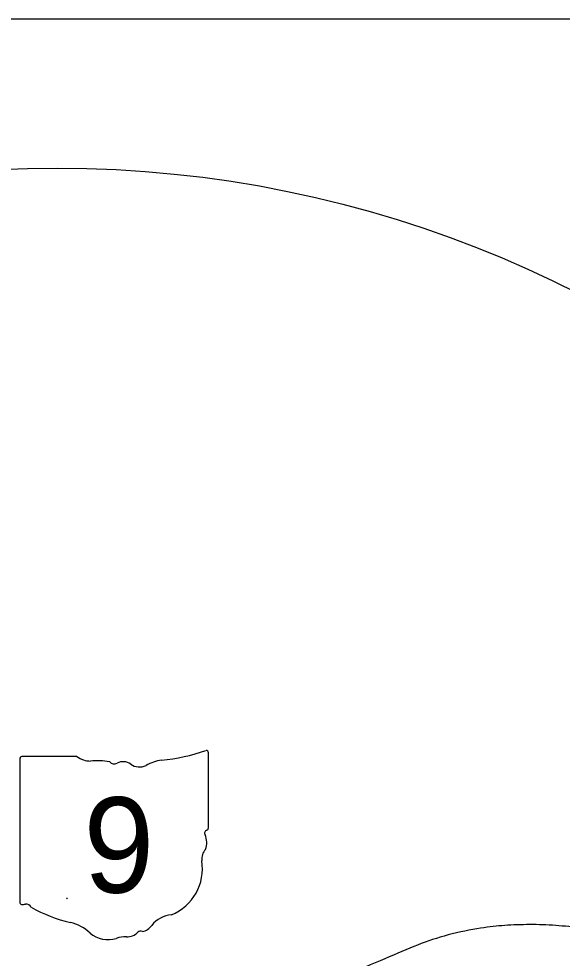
# Model space of a CAD drawing. Extents: x -740 to 1519, y 0 to 440.
# Drawn here: x 492 to 534.8, y 146.1 to 220 of the extents above; entities that cross this region are included whole.
import ezdxf

# ---------------------------------------------------------------- set-up
doc = ezdxf.new("R2010")
doc.units = 0
for name, color, linetype in [('GM_X_County_Road_Text', 7, 'Continuous'), ('GM_X_Section', 7, 'Continuous'), ('GM_X_Section_Text', 7, 'Continuous'), ('SH_Data', 7, 'Continuous')]:
    doc.layers.add(name, color=color, linetype=linetype)

msp = doc.modelspace()

# ---------------------------------------------------------------- linework, layer by layer
at = {"layer": 'GM_X_County_Road_Text'}
for p, q in [((496.558, 161.954), (492.215, 161.954)), ((506.9, 156.344), (506.9, 162.233)), ((492.069, 161.76), (492.069, 150.504)), ((506.899, 156.346), (506.9, 156.344))]:
    msp.add_line(p, q, dxfattribs=at)
for centre, radius, start, end in [((492.239, 161.784), 0.172, 98.1301, 188.1301), ((497.593, 163.261), 1.667, 231.61951, 271.11188), ((501.617, 177.301), 15.728, 275.84447, 288.90645), ((506.736, 162.257), 0.165, 351.86209, 97.738), ((498.145, 155.634), 5.983, 80.48669, 94.98827), ((499.503, 161.843), 0.481, 219.79206, 297.10237), ((500.209, 160.542), 1, 54.46668, 119.14113), ((501.499, 162.326), 1.203, 233.85621, 294.82819), ((503.623, 158.516), 3.164, 97.34618, 120.76885), ((506.862, 155.912), 0.256, 107.94398, 210.33697), ((506.724, 156.322), 0.177, 289.60381, 7.73413), ((505.236, 155.168), 1.534, 340.03296, 23.64957), ((507.492, 153.88), 1.116, 136.8065, 186.92959), ((502.498, 153.131), 3.934, 292.30889, 8.98584), ((492.24, 150.479), 0.173, 171.95839, 258.30661), ((492.267, 151.631), 1.323, 267.33899, 280.60386), ((492.537, 149.854), 0.477, 29.74838, 93.27175), ((498.559, 159.968), 11.358, 240.41292, 257.1985), ((504.157, 147.343), 2.155, 94.40312, 142.57675), ((495.173, 145.446), 3.554, 47.18416, 75.83597), ((501.427, 149.413), 1.271, 282.87319, 323.27711), ((499.017, 149.798), 2.255, 230.70037, 286.29184), ((500.484, 148.955), 1.201, 268.77702, 315.54927), ((501.571, 147.865), 0.338, 65.75173, 132.64842), ((500.32, 145.906), 1.853, 85.69512, 111.20995)]:
    msp.add_arc(centre, radius, start, end, dxfattribs=at)
at = {"layer": 'GM_X_Section'}
msp.add_line((30, 220), (640, 220), dxfattribs=at)
at = {"layer": 'GM_X_Section_Text'}
for p, q in [((501.12, 152.325), (501.12, 152.34)), ((501.122, 152.34), (501.122, 152.337)), ((501.122, 152.335), (501.122, 152.325)), ((501.129, 152.339), (501.129, 152.339)), ((501.13, 152.329), (501.13, 152.329)), ((495.763, 150.795), (495.754, 150.782)), ((495.769, 150.78), (495.769, 150.78)), ((495.775, 150.786), (495.777, 150.786)), ((495.777, 150.784), (495.775, 150.784)), ((495.78, 150.785), (495.78, 150.785)), ((495.785, 150.78), (495.785, 150.78))]:
    msp.add_line(p, q, dxfattribs=at)
for points in [[(495.755, 150.779), (495.764, 150.779), (495.764, 150.775)], [(495.768, 150.781), (495.766, 150.781), (495.766, 150.795)], [(495.766, 150.775), (495.766, 150.779), (495.768, 150.779)]]:
    msp.add_lwpolyline(points, dxfattribs=at)
msp.add_lwpolyline([(495.764, 150.794), (495.764, 150.781), (495.756, 150.781), (495.764, 150.794)], close=True, dxfattribs=at)
for points in [[(501.12, 152.34), (501.12, 152.34), (501.121, 152.34)], [(501.12, 152.326), (501.12, 152.327), (501.12, 152.327)], [(501.12, 152.327), (501.12, 152.327), (501.12, 152.327)], [(501.12, 152.327), (501.12, 152.327), (501.12, 152.327)], [(501.12, 152.327), (501.121, 152.327), (501.121, 152.327)], [(501.121, 152.325), (501.12, 152.326), (501.12, 152.326)], [(501.12, 152.326), (501.12, 152.326), (501.12, 152.326)], [(501.121, 152.325), (501.12, 152.325), (501.12, 152.325)], [(501.121, 152.34), (501.121, 152.34), (501.121, 152.34)], [(501.121, 152.34), (501.121, 152.34), (501.121, 152.34)], [(501.121, 152.34), (501.121, 152.34), (501.121, 152.34)], [(501.121, 152.34), (501.122, 152.34), (501.122, 152.34)], [(501.121, 152.338), (501.121, 152.338), (501.122, 152.339)], [(501.121, 152.336), (501.121, 152.337), (501.121, 152.338)], [(501.121, 152.334), (501.121, 152.335), (501.121, 152.336)], [(501.122, 152.333), (501.121, 152.334), (501.121, 152.334)], [(501.121, 152.327), (501.121, 152.327), (501.121, 152.327)], [(501.121, 152.327), (501.122, 152.327), (501.122, 152.327)], [(501.122, 152.325), (501.122, 152.325), (501.121, 152.325)], [(501.121, 152.325), (501.121, 152.325), (501.121, 152.325)], [(501.121, 152.324), (501.121, 152.324), (501.121, 152.325)], [(501.122, 152.324), (501.122, 152.324), (501.121, 152.324)], [(501.121, 152.324), (501.121, 152.324), (501.121, 152.324)], [(501.121, 152.324), (501.121, 152.324), (501.121, 152.324)], [(501.122, 152.339), (501.123, 152.339), (501.124, 152.34)], [(501.122, 152.34), (501.122, 152.34), (501.122, 152.34)], [(501.122, 152.34), (501.122, 152.34), (501.122, 152.34)], [(501.122, 152.34), (501.122, 152.34), (501.122, 152.34)], [(501.122, 152.337), (501.123, 152.338), (501.124, 152.339)], [(501.124, 152.336), (501.123, 152.336), (501.122, 152.335)], [(501.123, 152.332), (501.122, 152.333), (501.122, 152.333)], [(501.122, 152.327), (501.123, 152.326), (501.123, 152.326)], [(501.123, 152.324), (501.123, 152.324), (501.122, 152.325)], [(501.122, 152.325), (501.122, 152.325), (501.122, 152.325)], [(501.122, 152.325), (501.122, 152.324), (501.122, 152.324)], [(501.122, 152.324), (501.122, 152.324), (501.122, 152.324)], [(501.124, 152.338), (501.124, 152.338), (501.123, 152.338)], [(501.123, 152.338), (501.123, 152.338), (501.123, 152.337)], [(501.123, 152.337), (501.123, 152.337), (501.123, 152.336)], [(501.123, 152.336), (501.123, 152.335), (501.123, 152.335)], [(501.123, 152.335), (501.123, 152.334), (501.124, 152.334)], [(501.125, 152.332), (501.124, 152.332), (501.123, 152.332)], [(501.123, 152.326), (501.124, 152.326), (501.125, 152.326)], [(501.125, 152.324), (501.124, 152.324), (501.123, 152.324)], [(501.124, 152.34), (501.124, 152.34), (501.126, 152.34)], [(501.124, 152.339), (501.124, 152.339), (501.125, 152.34)], [(501.126, 152.339), (501.125, 152.339), (501.124, 152.338)], [(501.125, 152.338), (501.124, 152.337), (501.124, 152.336)], [(501.124, 152.334), (501.124, 152.334), (501.125, 152.333)], [(501.125, 152.34), (501.125, 152.34), (501.126, 152.34)], [(501.126, 152.338), (501.126, 152.338), (501.125, 152.338)], [(501.125, 152.338), (501.125, 152.338), (501.125, 152.338)], [(501.125, 152.333), (501.126, 152.333), (501.126, 152.333)], [(501.126, 152.331), (501.125, 152.331), (501.125, 152.332)], [(501.125, 152.326), (501.126, 152.326), (501.126, 152.326)], [(501.127, 152.324), (501.126, 152.324), (501.125, 152.324)], [(501.126, 152.34), (501.126, 152.34), (501.127, 152.34)], [(501.126, 152.34), (501.126, 152.34), (501.126, 152.34)], [(501.126, 152.34), (501.127, 152.34), (501.127, 152.34)], [(501.127, 152.338), (501.126, 152.339), (501.126, 152.339)], [(501.127, 152.338), (501.127, 152.338), (501.126, 152.338)], [(501.126, 152.333), (501.127, 152.333), (501.128, 152.332)], [(501.127, 152.331), (501.127, 152.331), (501.126, 152.331)], [(501.126, 152.326), (501.127, 152.326), (501.127, 152.326)], [(501.127, 152.34), (501.127, 152.34), (501.128, 152.34)], [(501.127, 152.34), (501.127, 152.34), (501.128, 152.34)], [(501.128, 152.338), (501.128, 152.338), (501.127, 152.338)], [(501.128, 152.338), (501.127, 152.338), (501.127, 152.338)], [(501.128, 152.33), (501.128, 152.33), (501.127, 152.331)], [(501.127, 152.326), (501.128, 152.327), (501.128, 152.327)], [(501.129, 152.325), (501.128, 152.325), (501.127, 152.324)], [(501.128, 152.34), (501.128, 152.34), (501.129, 152.34)], [(501.128, 152.34), (501.128, 152.34), (501.128, 152.34)], [(501.128, 152.34), (501.128, 152.34), (501.128, 152.34)], [(501.128, 152.34), (501.129, 152.34), (501.129, 152.34)], [(501.129, 152.338), (501.129, 152.338), (501.128, 152.338)], [(501.129, 152.338), (501.128, 152.338), (501.128, 152.338)], [(501.128, 152.338), (501.128, 152.338), (501.128, 152.338)], [(501.128, 152.338), (501.128, 152.338), (501.128, 152.338)], [(501.128, 152.332), (501.129, 152.332), (501.129, 152.331)], [(501.128, 152.329), (501.128, 152.329), (501.128, 152.33)], [(501.128, 152.327), (501.128, 152.328), (501.128, 152.329)], [(501.129, 152.34), (501.129, 152.339), (501.129, 152.339)], [(501.129, 152.34), (501.129, 152.34), (501.129, 152.339)], [(501.129, 152.339), (501.129, 152.339), (501.129, 152.339)], [(501.129, 152.339), (501.129, 152.339), (501.13, 152.339)], [(501.129, 152.339), (501.129, 152.339), (501.129, 152.338)], [(501.129, 152.339), (501.129, 152.339), (501.129, 152.339)], [(501.129, 152.339), (501.129, 152.339), (501.129, 152.339)], [(501.13, 152.338), (501.13, 152.338), (501.129, 152.338)], [(501.129, 152.338), (501.129, 152.338), (501.129, 152.337)], [(501.129, 152.337), (501.129, 152.337), (501.129, 152.338)], [(501.129, 152.338), (501.129, 152.338), (501.129, 152.338)], [(501.129, 152.338), (501.129, 152.338), (501.129, 152.338)], [(501.129, 152.337), (501.129, 152.337), (501.129, 152.337)], [(501.129, 152.331), (501.13, 152.331), (501.13, 152.33)], [(501.13, 152.327), (501.13, 152.326), (501.129, 152.325)], [(501.13, 152.339), (501.13, 152.339), (501.13, 152.339)], [(501.13, 152.339), (501.13, 152.338), (501.13, 152.338)], [(501.13, 152.338), (501.13, 152.338), (501.13, 152.338)], [(501.13, 152.33), (501.13, 152.33), (501.13, 152.329)], [(501.13, 152.329), (501.13, 152.328), (501.13, 152.327)], [(495.754, 150.782), (495.754, 150.781), (495.754, 150.781)], [(495.754, 150.781), (495.754, 150.781), (495.754, 150.781)], [(495.754, 150.781), (495.754, 150.781), (495.754, 150.781)], [(495.754, 150.781), (495.754, 150.78), (495.754, 150.78)], [(495.754, 150.78), (495.754, 150.78), (495.754, 150.78)], [(495.754, 150.78), (495.754, 150.78), (495.754, 150.78)], [(495.754, 150.78), (495.754, 150.779), (495.754, 150.779)], [(495.754, 150.779), (495.754, 150.779), (495.755, 150.779)], [(495.764, 150.796), (495.763, 150.796), (495.763, 150.795)], [(495.763, 150.795), (495.763, 150.795), (495.763, 150.795)], [(495.763, 150.795), (495.763, 150.795), (495.763, 150.795)], [(495.765, 150.796), (495.764, 150.796), (495.764, 150.796)], [(495.764, 150.796), (495.764, 150.796), (495.764, 150.796)], [(495.764, 150.775), (495.764, 150.774), (495.764, 150.774)], [(495.764, 150.774), (495.764, 150.774), (495.764, 150.774)], [(495.764, 150.774), (495.764, 150.774), (495.764, 150.774)], [(495.764, 150.774), (495.764, 150.774), (495.765, 150.774)], [(495.765, 150.795), (495.765, 150.795), (495.765, 150.796)], [(495.766, 150.795), (495.765, 150.795), (495.765, 150.795)], [(495.765, 150.774), (495.765, 150.774), (495.765, 150.774)], [(495.765, 150.774), (495.765, 150.774), (495.765, 150.774)], [(495.765, 150.774), (495.766, 150.774), (495.766, 150.774)], [(495.766, 150.795), (495.766, 150.795), (495.766, 150.795)], [(495.766, 150.774), (495.766, 150.774), (495.766, 150.775)], [(495.769, 150.781), (495.769, 150.781), (495.768, 150.781)], [(495.768, 150.779), (495.769, 150.779), (495.769, 150.78)], [(495.769, 150.78), (495.769, 150.781), (495.769, 150.781)], [(495.769, 150.78), (495.769, 150.78), (495.769, 150.78)], [(495.772, 150.776), (495.772, 150.776), (495.772, 150.777)], [(495.772, 150.777), (495.772, 150.777), (495.772, 150.777)], [(495.772, 150.777), (495.772, 150.777), (495.772, 150.777)], [(495.772, 150.777), (495.772, 150.777), (495.773, 150.777)], [(495.772, 150.775), (495.772, 150.776), (495.772, 150.776)], [(495.772, 150.776), (495.772, 150.776), (495.772, 150.776)], [(495.772, 150.776), (495.772, 150.776), (495.772, 150.776)], [(495.773, 150.775), (495.772, 150.775), (495.772, 150.775)], [(495.773, 150.793), (495.773, 150.793), (495.773, 150.794)], [(495.773, 150.794), (495.773, 150.794), (495.773, 150.794)], [(495.773, 150.794), (495.773, 150.794), (495.773, 150.794)], [(495.773, 150.794), (495.773, 150.794), (495.774, 150.794)], [(495.773, 150.792), (495.773, 150.792), (495.773, 150.793)], [(495.773, 150.793), (495.773, 150.793), (495.773, 150.793)], [(495.773, 150.793), (495.773, 150.793), (495.773, 150.793)], [(495.774, 150.792), (495.773, 150.792), (495.773, 150.792)], [(495.773, 150.792), (495.773, 150.792), (495.773, 150.792)], [(495.773, 150.792), (495.773, 150.792), (495.773, 150.792)], [(495.773, 150.777), (495.773, 150.777), (495.774, 150.777)], [(495.774, 150.775), (495.773, 150.775), (495.773, 150.775)], [(495.774, 150.794), (495.774, 150.795), (495.775, 150.795)], [(495.775, 150.793), (495.774, 150.793), (495.774, 150.792)], [(495.774, 150.785), (495.774, 150.785), (495.774, 150.786)], [(495.774, 150.786), (495.774, 150.786), (495.774, 150.786)], [(495.774, 150.786), (495.774, 150.786), (495.775, 150.786)], [(495.774, 150.784), (495.774, 150.785), (495.774, 150.785)], [(495.774, 150.785), (495.774, 150.785), (495.774, 150.785)], [(495.775, 150.784), (495.774, 150.784), (495.774, 150.784)], [(495.774, 150.777), (495.775, 150.776), (495.776, 150.776)], [(495.776, 150.774), (495.775, 150.774), (495.774, 150.775)], [(495.775, 150.795), (495.775, 150.795), (495.776, 150.796)], [(495.776, 150.794), (495.775, 150.793), (495.775, 150.793)], [(495.775, 150.786), (495.775, 150.786), (495.775, 150.786)], [(495.775, 150.784), (495.775, 150.784), (495.775, 150.784)], [(495.776, 150.796), (495.777, 150.796), (495.778, 150.796)], [(495.778, 150.794), (495.777, 150.794), (495.776, 150.794)], [(495.776, 150.776), (495.777, 150.776), (495.778, 150.776)], [(495.778, 150.774), (495.777, 150.774), (495.776, 150.774)], [(495.777, 150.786), (495.778, 150.786), (495.779, 150.786)], [(495.779, 150.784), (495.778, 150.784), (495.777, 150.784)], [(495.778, 150.796), (495.78, 150.796), (495.781, 150.795)], [(495.78, 150.794), (495.779, 150.794), (495.778, 150.794)], [(495.778, 150.776), (495.779, 150.776), (495.78, 150.776)], [(495.781, 150.774), (495.779, 150.774), (495.778, 150.774)], [(495.779, 150.786), (495.78, 150.787), (495.78, 150.787)], [(495.781, 150.783), (495.78, 150.784), (495.779, 150.784)], [(495.781, 150.793), (495.78, 150.793), (495.78, 150.794)], [(495.78, 150.787), (495.781, 150.788), (495.781, 150.789)], [(495.781, 150.786), (495.781, 150.786), (495.78, 150.785)], [(495.78, 150.785), (495.781, 150.785), (495.782, 150.785)], [(495.78, 150.776), (495.781, 150.776), (495.781, 150.777)], [(495.781, 150.795), (495.782, 150.795), (495.782, 150.794)], [(495.781, 150.792), (495.781, 150.792), (495.781, 150.793)], [(495.782, 150.79), (495.782, 150.791), (495.781, 150.792)], [(495.781, 150.789), (495.782, 150.789), (495.782, 150.79)], [(495.783, 150.787), (495.782, 150.786), (495.781, 150.786)], [(495.782, 150.782), (495.782, 150.783), (495.781, 150.783)], [(495.781, 150.777), (495.782, 150.777), (495.782, 150.778)], [(495.783, 150.776), (495.782, 150.775), (495.781, 150.774)], [(495.782, 150.794), (495.783, 150.794), (495.783, 150.793)], [(495.782, 150.785), (495.783, 150.784), (495.783, 150.784)], [(495.783, 150.78), (495.783, 150.781), (495.782, 150.782)], [(495.782, 150.778), (495.783, 150.779), (495.783, 150.78)], [(495.783, 150.793), (495.784, 150.792), (495.784, 150.791)], [(495.784, 150.789), (495.783, 150.788), (495.783, 150.787)], [(495.783, 150.784), (495.784, 150.783), (495.784, 150.782)], [(495.784, 150.778), (495.784, 150.777), (495.783, 150.776)], [(495.784, 150.791), (495.784, 150.79), (495.784, 150.789)], [(495.784, 150.782), (495.785, 150.781), (495.785, 150.78)], [(495.785, 150.78), (495.785, 150.779), (495.784, 150.778)]]:
    msp.add_open_spline(points, degree=2, dxfattribs=at)
at = {"layer": 'SH_Data'}
msp.add_circle((495, 118.25), 90, dxfattribs=at)
msp.add_open_spline([(591.92, 157.705), (590.626, 153.517), (588.033, 149.489), (581.373, 145.107), (566.146, 145.009), (547.531, 146.268), (529.802, 149.818), (516.164, 144.084), (497.291, 136.276)], degree=2, dxfattribs=at)

# ---------------------------------------------------------------- texts
at = {"layer": 'GM_X_County_Road_Text'}
msp.add_text('9', height=7.5, dxfattribs=at).set_placement((497.067, 151.237))

doc.saveas('drawing.dxf')
